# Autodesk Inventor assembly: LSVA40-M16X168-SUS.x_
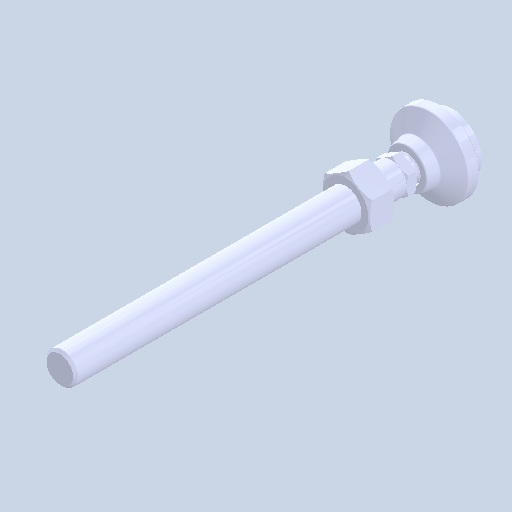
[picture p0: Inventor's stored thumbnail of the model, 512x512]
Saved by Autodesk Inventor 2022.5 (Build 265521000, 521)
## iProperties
Created: 2024-08
Part Number: LSVA40-M16X168-SUS.x_
Document SubType Name: Assembly
Designer: ImaoCorp
Author: ImaoCorp
Sending System: SOLIDWORKS 2022-2022290
MC: AMD64
MC_MODEL: Intel64 Family 6 Model 60 Stepping 3, GenuineIntel
OS: Windows_NT
FRU: Parasolid Version 33.1, build 260,  4-25-2022
FORMAT: text
GUISE: transmit
KEY: FILELSVA40-M16X168-SUS.x_t
DATE: Fri Aug 23 16:07:49 2024
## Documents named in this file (4)
- X:\14_SW2022-Inv2022\06_2024-10新製品(SME)\ELS_データ\l\lsva40-m16x168-sus\LSVA40-M16X168-SUS.x_.iam
- X:\14_SW2022-Inv2022\06_2024-10新製品(SME)\ELS_データ\l\lsva40-m16x168-sus\LSVA40-M16X168-SUS_01.ipt
- X:\14_SW2022-Inv2022\06_2024-10新製品(SME)\ELS_データ\l\lsva40-m16x168-sus\LSVA40-M16X168-SUS_02.ipt
- X:\14_SW2022-Inv2022\06_2024-10新製品(SME)\ELS_データ\l\lsva40-m16x168-sus\LSVA40-M16X168-SUS_03.ipt
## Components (3 placed, 3 different names)
1. LSVA40-M16X168-SUS_01
2. LSVA40-M16X168-SUS_02
3. LSVA40-M16X168-SUS_03
